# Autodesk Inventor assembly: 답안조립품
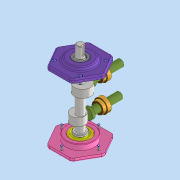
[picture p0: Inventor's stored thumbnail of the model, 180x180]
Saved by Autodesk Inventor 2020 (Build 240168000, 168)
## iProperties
Created: 2021-06
Part Number: 답안조립품
Document SubType Name: Assembly
Designer: MIRAE
Author: MIRAE
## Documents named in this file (11)
- C:\Users\MIRAE\Desktop\710606V1032\답안조립품.iam
- C:\Users\MIRAE\Desktop\710606V1032\본체.ipt
- C:\Users\MIRAE\Desktop\710606V1032\뒷커버.ipt
- C:\Users\MIRAE\Desktop\710606V1032\베어링 6203.ipt
- C:\Users\MIRAE\Desktop\710606V1032\베어링 6302.ipt
- C:\Users\MIRAE\Desktop\710606V1032\볼트 M4.ipt
- C:\Users\MIRAE\Desktop\710606V1032\부시.ipt
- C:\Users\MIRAE\Desktop\710606V1032\슬라이더.ipt
- C:\Users\MIRAE\Desktop\710606V1032\앞커버.ipt
- C:\Users\MIRAE\Desktop\710606V1032\오일실.ipt
- C:\Users\MIRAE\Desktop\710606V1032\편심축.ipt
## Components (10 placed, 3 different names)
1. 7-베어링 6203:1
2. 8-오일실:1
3. 9-M4-소켓머리:2 — 각도:1
4. 9-M4-소켓머리:3
5. 9-M4-소켓머리:4
6. 9-M4-소켓머리:5
7. 9-M4-소켓머리:1 — 각도:2
8. 9-M4-소켓머리:6
9. 9-M4-소켓머리:7
10. 9-M4-소켓머리:8
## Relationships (2: Angle 2)
- 각도:1 [Angle]: 9-M4-소켓머리:2
- 각도:2 [Angle]: 9-M4-소켓머리:1
